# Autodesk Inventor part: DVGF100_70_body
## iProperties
Created: 2010-04
Part Number: DVGF100_70_body
Document SubType Name: Modeling
Designer: TB
Mass: 2195.3 g
Surface Area: 2630.8 cm^2
Volume: 2195.3 cm^3
Density: 1 g/cm^3
Author: TB
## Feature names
1. Kropp [Revolution]
2. Chamfer
3. Extrusion2
4. Hole1
5. Revolution2
6. Hole2
7. Fillet1
8. Extrusion3
9. Hole3
